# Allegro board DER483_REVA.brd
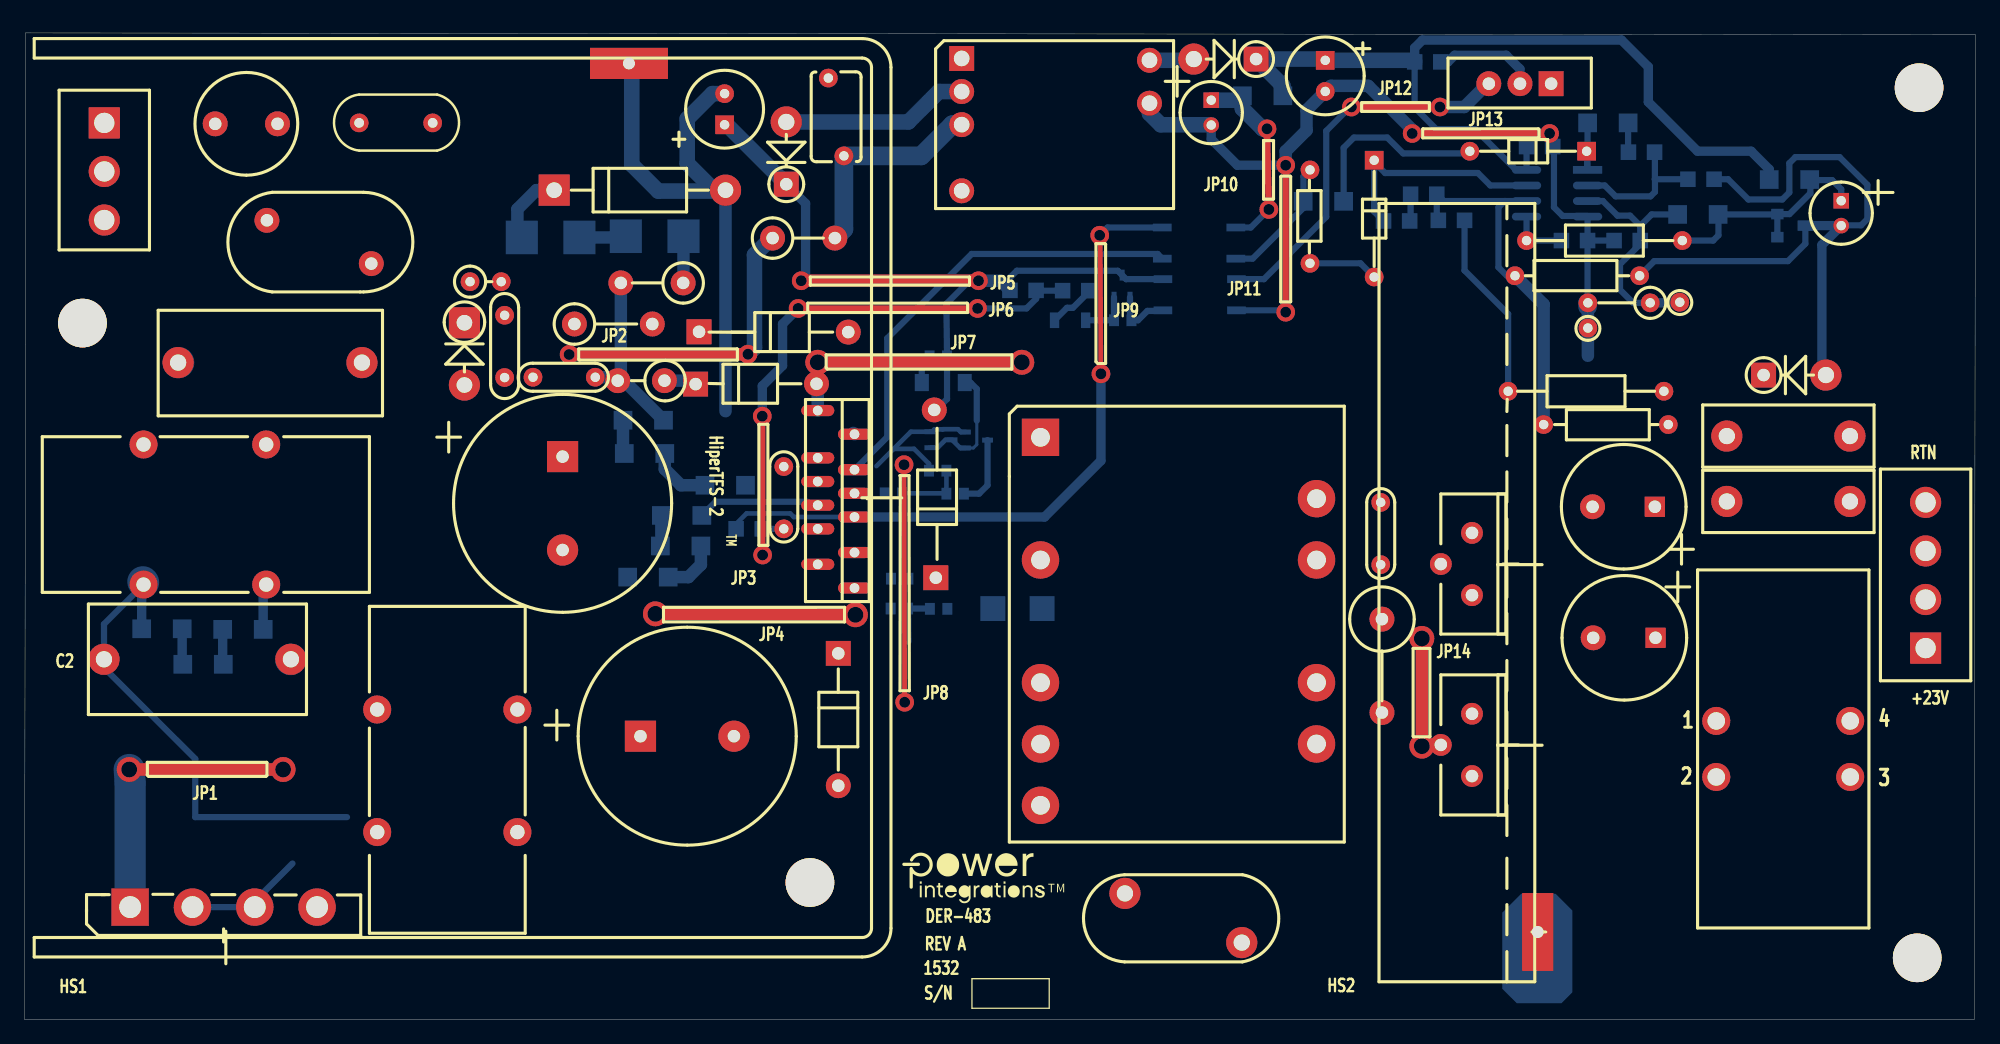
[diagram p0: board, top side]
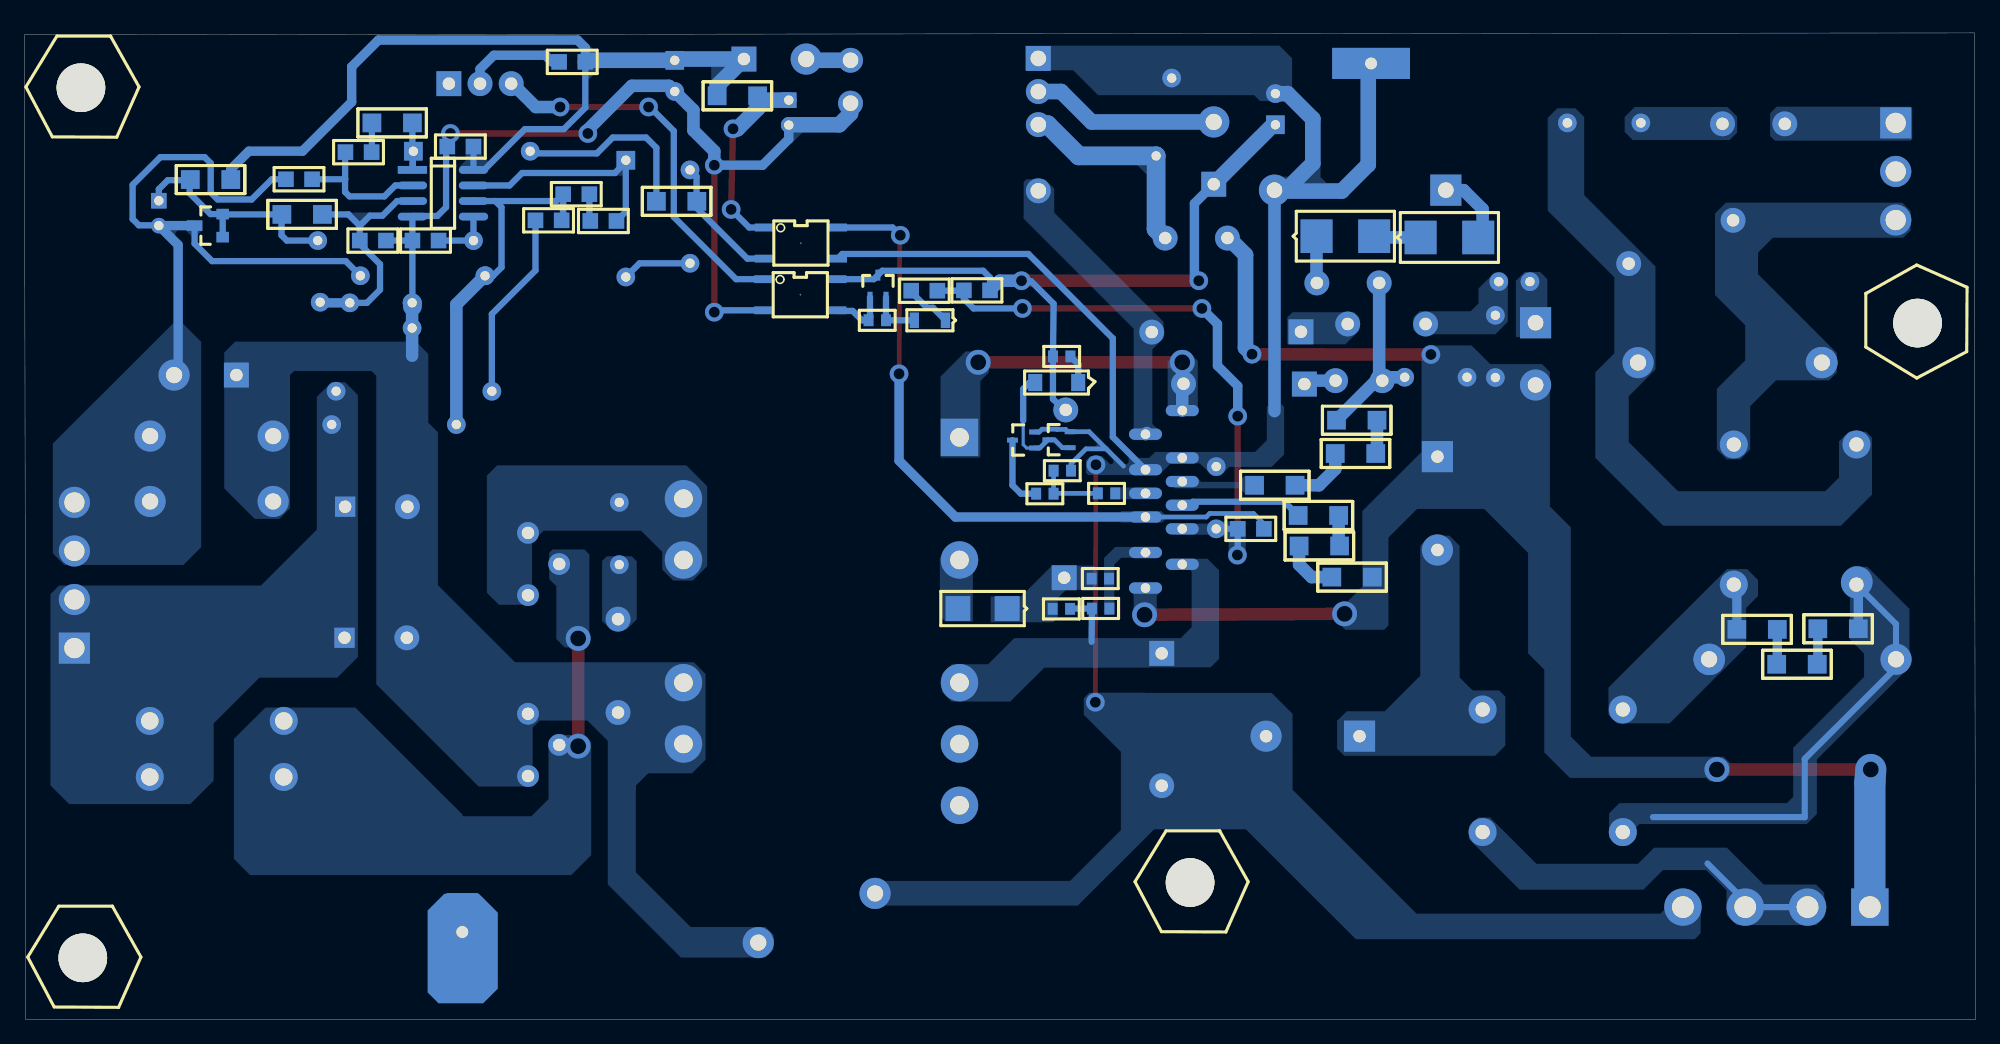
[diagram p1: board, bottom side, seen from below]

Outline 159.05 x 80.49 mm; copper layers: TOP, BOTTOM. Coordinates in mm from the lower left corner of the outline.
Outline path: 0,0 0.08,55.09 0.08,80.49 159.05,80.34 158.95,0 0,0

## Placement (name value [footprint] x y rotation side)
BR1  GBU8J  [PIDAXBRIDGEGBU8]  8.61 9.17 0 top
C1  220 nF  [PINPXCAPRAD720X340590040]  27.51 53.59 180 top
C2  470 nF  [PI_NP_CAP700X355LS600D040]  21.72 29.39 180 top
C3  560 uf  [PIPOLCAPCLYD710LS300040]  43.87 45.92 270 top
C4  560 uf  [PIPOLCAPCLYD710LS300040]  50.22 23.11 0 top
C5  2.2 nF  [PINPCAPRAD200X100200030]  46.53 52.4 180 top
C6  10 uF  [PINPCAPRAD200X100200030]  61.9 40.03 90 top
C7  100 nF  [PISMC0603]  70.61 33.53 0 bottom
C8  100 nF  [PISMC0603]  75.23 33.5 180 bottom
C9  2.2 nF  [PINPCAPRAD350X100200030]  39.14 52.37 90 top
C10  1.0 nF  [PINPCAPRAD290X160250030]  65.53 76.81 270 top
C11  10 nF  [PISMC0603]  75.16 44.78 180 bottom
C12  150 uF  [PIPOLCAPCYLD250LS100030]  57.07 73 90 top
C13  4.7 nF  [PINPCAPRAD640X260375040]  89.71 10.31 0 top
C14  1 nF  [PINPCAPRAD250X100200030]  110.57 42.19 270 top
C15  330 uF  [PIPOLCAPCYLD400LS200040]  132.97 31.14 180 top
C16  330 uF  [PIPOLCAPCYLD400LS200040]  132.92 41.83 180 top
C17  10 uF  [PIPOLCAPCLYD200LS80030]  96.75 75.01 270 top
C18  10 nf  [PISMC0805]  110.79 65.15 0 bottom
C19  2.2 nF  [PISMC0805]  115.27 65.2 0 bottom
C20  10 nf  [PISMC0805]  127.43 63.55 180 bottom
C21  150 uF  [PIPOLCAPCYLD250LS100030]  106.05 78.26 270 top
C22  10 nf  [PISMC0805]  130.76 70.76 0 bottom
C23  100 nF  [PISMC0805]  122.45 71.22 0 bottom
C24  100 nF  [PISMC0805]  129.59 63.55 0 bottom
C25  10 uF  [PIPOLCAPCLYD200LS80030]  148.11 66.8 270 top
D1  BAV19WS  [PISMSOD323]  83.97 57.05 0 bottom
D2  1N4007  [PIDAX475X125040DO41#2]  53.77 51.87 0 top
D3  US1D  [PISMDSMA]  78.94 33.53 0 bottom
D4  UF4005  [PIDAX475X125040DO41#3]  66.34 29.87 270 top
D5  UF4005  [PIDAX475X125040DO41]  74.3 36.04 90 top
D6  1N4007  [PIDV200X110X040DO41#2]  56.36 56.08 0 top
D7  UF4003  [PIDV200X110X040DO41]  62.1 68.15 90 top
D8  STPS30150CT  [PIDVTO2203VF1]  118.01 37.16 270 top
D9  STPS30150CT  [PIDVTO2203VF1]  118.01 22.4 270 top
D10  1N4148  [PIDAX375X070030DO35]  127.36 70.84 180 top
D11  1N4148  [PIDAX375X070030DO35]  110.03 70.1 270 top
D12  UF4003  [PIDV200X110X040DO41]  100.41 78.36 180 top
D13  1N4002-E3/54  [PIDV200X110X040DO41]  141.78 52.58 0 top
F1  5 A  [PI_TR5_SUBMIN_FUSE]  15.54 73.08 0 top
HS1  HEATSINK, W/PEM NUT AND EYELET, PI CUST  [PI_HS_DER483_BRIDGE_ESIP]  0.79 80.04 270 top
HS2  HEATSINK, W/PEM NUT AND EYELET, PI CUST  [PI_HS_DER483_DIODES]  123.14 3.07 90 top
J1  CON3  [PI_HDR_3PIN]  6.5 73.15 180 top
J2  CON4  [PI_HDR_4PIN]  154.99 30.3 0 top
J3  Rp  [PI_HOLE_30AWG]  127.46 56.41 0 top
J4  PCB Terminal 30 AWG  [PI_HOLE_30AWG]  134.95 58.52 0 top
L1  9 mH  [PI_IND_4P_500X1050LS450D46]  9.7 35.48 90 top
L2  9 mH  [PI_IND_4P_500X1050LS450D46]  40.18 15.29 180 top
L3  41 uH  [PI_IND_4P_TOROIDAL]  143.38 22.07 0 top
NOREF  -  []  -0.03 0.03 0 top
NOREF#2  -  []  -150.38 42.55 0 top
NOREF#3  -  []  -0.03 0.03 90 top
NOREF#4  -  []  71.58 14.05 0 top
NOREF#5  -  []  -228.19 -156.46 0 top
POST1  Post Hex, 6-32, snap, 0.375L, NYL  [PIMTGHOLED156]  64.03 11.18 180 bottom
POST2  Post Hex, 6-32, snap, 0.375L, NYL  [PIMTGHOLED156]  154.46 76.02 180 bottom
POST3  Post Hex, 6-32, snap, 0.375L, NYL  [PIMTGHOLED156]  154.31 5.03 180 bottom
POST4  Post Hex, 6-32, snap, 0.375L, NYL  [PIMTGHOLED156]  4.72 56.82 90 bottom
Q1  MMST3904  [PISMSOT323132]  76.71 46.61 90 bottom
Q2  MMST3904  [PISMSOT323132]  73.81 46.63 90 bottom
Q3  MMST3904  [PISMSOT323132]  90.14 58.93 180 bottom
R1  680 k  [PISMR1206]  9.55 31.88 0 bottom
R2  680 k  [PISMR1206]  12.9 28.98 0 bottom
R3  680 k  [PISMR1206]  16.15 31.83 0 bottom
R4  931 k  [PISMR1206]  52.48 36.09 180 bottom
R5  931 k  [PISMR1206]  55.14 38.63 180 bottom
R6  976 k  [PISMR1206]  51.92 41.12 0 bottom
R7  100  [PI12WRESD180LS675D040]  53.7 60.1 180 top
R8  2.2  [PI12WVRESD180LS150D040]  48.36 52.12 0 top
R9  931 k  [PISMR1206]  52.1 48.89 180 bottom
R10  931 k  [PISMR1206]  48.9 46.18 0 bottom
R11  976 k  [PISMR1206]  58.78 43.59 180 bottom
R12  7.5 k  [PISMR0805]  80.34 59.49 0 bottom
R13  47 k  [PISMR0603]  90.25 57.05 180 bottom
R14  1.2 k  [PISMR0805]  84.63 59.46 0 bottom
R15  232 k  [PISMR0805]  60.15 40.03 180 bottom
R16  1 k  [PISMR0603]  70.64 35.97 0 bottom
R17  22 k  [PI14WVRESD100LS100D030]  36.32 60.2 0 top
R18  6.8  [PI12WVRESD180LS150D040#2]  44.83 56.74 0 top
R19  2.2  [PI12WVRESD180LS150D040#3]  60.99 63.75 0 top
R20  4.7 k  [PISMR0603]  71.55 42.93 180 bottom
R21  4.7 k  [PISMR0603]  76.58 42.9 180 bottom
R22  1 k  [PISMR0603]  75.21 54.1 180 bottom
R23  4.7  [PI1WVRESD200LS200D040]  110.67 32.66 270 top
R24  220  [PISMR1206]  99.29 75.36 0 bottom
R25  4.7 k  [PISMR1206]  107.54 66.75 180 bottom
R26  3.3 k  [PI18WRESD080LS300D030]  104.8 69.32 270 top
R27  82.5 k  [PI14WRESD100LS500D030]  134.01 48.54 180 top
R28  10 k  [PI14WVRESD100LS100D030#2]  120.95 51.26 0 top
R29  3.3 k  [PISMR0805]  113 67.34 0 bottom
R30  10.0 k  [PI14WRESD100LS400D030]  121.51 60.68 0 top
R31  4.7 k  [PI14WRESD100LS500D030#2]  135.15 63.55 180 top
R32  4.7 k  [PISMR1206]  142.24 68.53 0 bottom
R33  105 k  [PISMR1206]  134.77 65.68 0 bottom
R34  6.8 k  [PISMR1206]  127.43 73.15 0 bottom
R35  10 k  [PISMR0805]  135.61 68.55 0 bottom
R36  5.11 k  [PI14WRESD100LS400D030#2]  132.54 58.47 180 top
R37  0.03  [PI_5W_RES_550X200LS394D040]  138.79 42.27 0 top
R38  0.03  [PI_5W_RES_550X200LS394D040]  138.79 47.6 0 top
R39  10 k  [PISMR0805]  113.33 78.13 0 bottom
RT1  2.5  [PI_RAD180X395LS235D031]  27.28 73.15 0 top
RV1  175 VAC  [PI_DISC_575X320_LS335X140D040]  28.27 61.67 180 top
SW1  SPDT SLIDE  [PI_SWITCH_SPDT_SLIDE_PCBM_1]  124.46 76.35 90 top
T1  EER28L  [PI_BOBBIN_EER28L_14P_DER483]  82.83 47.5 0 top
T2  EF12.6  [PI_BOBBIN_EF126_9P_DER483]  76.4 78.41 0 top
U1  TFS-7704H  [PI_IC_ESIP16-12_OVAL_SLOT]  67.67 49.68 270 top
U2  PC357A  [PI_4_SMD]  95.76 63.35 270 bottom
U3  PC357A  [PI_4_SMD]  95.81 59.13 270 bottom
U4  LM431AIM3DR  [PISMSOT23123]  142.9 65.71 90 bottom
U5  LM358D  [PISMSO8]  127.43 69.32 270 bottom
VR1  SMBJ150A  [PISMDO214AA12]  53.72 63.91 180 bottom
VR2  MMSZ5245B-7-F  [PI_SM_SOD-123_12]  73.15 51.97 0 bottom
VR3  P6KE150A  [PIDV200X140X050DO15DO204AC]  35.86 56.85 270 top
VR5  SMBJ150A  [PISMDO214AA12]  45.24 63.8 180 bottom
VR6  P6KE170A  [PIDAX550X140050DO15DO204AC]  43.18 67.67 0 top

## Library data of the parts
BR1 = DISCRETE BRIDGE_+~~-
C1 C5-C11 C13 C14 C18-C20 C22-C24 = CAP NP
C2 = CAP NP: tolerance: 20
C3 C4 = CAP POL
C12 C21 = CAP POL: tolerance: 20
C15 C16 = CAP POL: alternate symbols: (pipolcapclyd395x630ls200030h)
C17 C25 = CAP POL: alternate symbols: (pipolcapclyd200ls80030h)
D1 D3 = DIODE
D2 D6 D7 D12 D13 = DIODE: alternate symbols: (pidax475x125040do41,pidv200x110x040do41wbead,pidax390x125040do41)
D4 D5 = DIODE: alternate symbols: (pidax475x125040do41,pidax390x125040do41)
D8 D9 = DS_DUAL_CK_A_AC: alternate symbols: (pidvto2203vf1)
D10 D11 = DIODE: alternate symbols: (pidax375x070030do35,pidv100x080x030do35)
F1 = FUSE
HS1 HS2 = HS-PI_CUSTOM1
J1 = CON3
J2 = CON4
J3 J4 = TERM_1Pin
L1 L2 = INDUCTOR_4P_REVB_0
L3 = INDUCTOR_4P_SD
POST1-POST4 = POST_CRKT_BRD_6-32_HEX
Q1-Q3 = NPN_BEC
R1-R4 R9-R15 R20-R22 R24 R25 R29 R32-R34 R37-R39 = R
R5 R6 R35 = R: tolerance: 1%
R7 R8 R18 R19 = R: alternate symbols: (pi12wvresd180ls200d040,pi12wvresd180ls250d040,pi12wresd180ls675d040)
R16 = R: tolerance: 5%
R17 R27 R28 R30 R31 R36 = R: alternate symbols: (pi14wvresd100ls200d030,pi14wresd100ls400d030,pi14wresd100ls500d030)
R23 = R: alternate symbols: (pi1wvresd120ls200d040,pi1wvresd120ls300d040,pi1wvresd200ls200d040,pi1wvresd200ls300d040,pi1wvresd200ls350d040)
R26 = R: alternate symbols: (pi18wresd080ls300d030)
RT1 = THERMISTOR
RV1 = VARISTOR
SW1 = SW SLIDE-SPDT
T1 = BEER28L_CUSTOM_DER483
T2 = BEF12.6_CUSTOM_DER483
U1 = HiperTFS_II_I_2_ROW_2: alternate symbols: (pi_ic_esip16-12_oval_slot_recpt)
U2 U3 = OPTO_A_B
U4 = TL431/SOT-23_CAR: tolerance: 2%
U5 = LM358
VR1 VR2 VR5 = DIODE_ZENER
VR3 VR6 = DIODE_ZENER: alternate symbols: (pidax550x140050do15do204ac)

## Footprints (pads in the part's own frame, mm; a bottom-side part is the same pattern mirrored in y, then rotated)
PI1WVRESD200LS200D040
  round 2.032 hole 1.016: 1(0,0) 2(7.62,0)
PI12WRESD180LS675D040
  round 2.032 hole 1.016: 1(0,0) 2(5.08,0)
PI12WVRESD180LS150D040
  round 2.032 hole 1.016: 1(0,0) 2(3.81,0)
PI12WVRESD180LS150D040#2
  round 2.032 hole 1.016: 1(0,0) 2(6.35,0)
PI12WVRESD180LS150D040#3
  round 2.032 hole 1.016: 1(0,0) 2(5.08,0)
PI14WRESD100LS400D030
  round 1.524 hole 0.762: 1(0,0) 2(10.16,0)
PI14WRESD100LS400D030#2
  round 1.524 hole 0.762: 1(0,0) 2(5.08,0)
PI14WRESD100LS500D030
  round 1.524 hole 0.762: 1(0,0) 2(10.16,0)
PI14WRESD100LS500D030#2
  round 1.524 hole 0.762: 1(0,0) 2(12.7,0)
PI14WVRESD100LS100D030
  round 1.524 hole 0.762: 1(0,0) 2(2.54,0)
PI14WVRESD100LS100D030#2
  round 1.524 hole 0.762: 1(0,0) 2(12.7,0)
PI18WRESD080LS300D030
  round 1.524 hole 0.762: 1(0,0) 2(7.62,0)
PI_4_SMD
  rect 0.635x1.524 smd: 1(-1.27,-2.997) 2(1.27,-2.997) 3(1.27,2.997) 4(-1.27,2.997)
PI_5W_RES_550X200LS394D040
  round 2.54 hole 1.321: 1(0,0) 2(10.033,0)
PI_BOBBIN_EER28L_14P_DER483
  round 3.048 hole 1.524: (0,-25.019) (0,-30.023) 3(0,-10.008) 5(0,-20.015) 9(22.504,-25.019) 10(22.504,-20.015) 12(22.504,-10.008) 13(22.504,-5.004)
  rect 3.048x3.048 hole 1.524: 1(0,0)
PI_BOBBIN_EF126_9P_DER483
  rect 2.032x2.032 hole 1.27: 1(0,0)
  round 2.032 hole 1.27: 2(0,-2.7) 3(0,-5.4) 5(0,-10.8) 8(15.311,-3.65) 9(15.311,-0.15)
PI_DISC_575X320_LS335X140D040
  round 2.032 hole 1.016: 1(0,0) 2(8.509,-3.531)
PI_HDR_3PIN
  rect 2.54x2.54 hole 1.651: 1(0,0)
  round 2.54 hole 1.651: 2(0,3.962) 3(0,7.925)
PI_HDR_4PIN
  rect 2.54x2.54 hole 1.651: 1(0,0)
  round 2.54 hole 1.651: 2(0,3.962) 3(0,7.925) 4(0,11.887)
PI_HOLE_30AWG
  round 1.524 hole 0.762: 1(0,0)
PI_HS_DER483_BRIDGE_ESIP
  rect 2.54x6.35 hole 0.965: 1(2.032,48.489)
PI_HS_DER483_DIODES
  rect 6.35x2.54 hole 0.965: 1(4.064,-0.229)
PI_IC_ESIP16-12_OVAL_SLOT
  oval 0.914x2.692 hole 0.787: 1(0,-2.997) 3(1.93,0) 5(3.861,-2.997) 6(4.826,0) 7(5.791,-2.997) 8(6.756,0) 9(7.722,-2.997) 10(8.687,0) 11(9.652,-2.997) 13(11.582,0) 14(12.548,-2.997) 16(14.478,0)
PI_IND_4P_500X1050LS450D46
  round 2.286 hole 1.168: 1(0,0) 2(11.43,-10) 3(11.43,0) 4(0,-10)
PI_IND_4P_TOROIDAL
  round 2.286 hole 1.422: 1(-5.461,2.286) 2(-5.461,-2.286) 3(5.461,-2.286) 4(5.461,2.286)
PI_NP_CAP700X355LS600D040
  round 2.54 hole 1.321: 1(0,0) 2(15.24,0)
PI_RAD180X395LS235D031
  round 1.524 hole 0.787: 1(0,0) 2(5.994,0)
PI_SM_SOD-123_12
  rect 1.143x1.397 smd: 1(0,0) 2(3.505,0)
PI_SWITCH_SPDT_SLIDE_PCBM_1
  rect 2.032x2.032 hole 1.016: 1(0,0)
  round 2.032 hole 1.016: 2(0,2.54) 3(0,5.08)
PI_TR5_SUBMIN_FUSE
  round 2.032 hole 1.016: 1(0,0) 2(5.08,0)
PIDAX375X070030DO35
  rect 1.524x1.524 hole 0.762: 1(0,0)
  round 1.524 hole 0.762: 2(9.525,0)
PIDAX475X125040DO41
  rect 2.032x2.032 hole 1.016: 1(0,0)
  round 2.032 hole 1.016: 2(13.691,0.127)
PIDAX475X125040DO41#2
  rect 2.032x2.032 hole 1.016: 1(0.94,-0.025)
  round 2.032 hole 1.016: 2(10.795,0)
PIDAX475X125040DO41#3
  rect 2.032x2.032 hole 1.016: 1(0,0)
  round 2.032 hole 1.016: 2(10.795,0)
PIDAX550X140050DO15DO204AC
  rect 2.54x2.54 hole 1.27: 1(0,0)
  round 2.54 hole 1.27: 2(13.97,0)
PIDAXBRIDGEGBU8
  rect 3.048x3.048 hole 1.778: 1(0,0)
  round 3.048 hole 1.778: 2(5.08,0) 3(10.16,0) 4(15.24,0)
PIDV200X110X040DO41
  rect 2.032x2.032 hole 1.016: 1(0,0)
  round 2.54 hole 1.321: 2(5.08,0)
PIDV200X110X040DO41#2
  rect 2.032x2.032 hole 1.016: 1(-1.372,0.025)
  round 2.032 hole 1.016: 2(10.795,0)
PIDV200X140X050DO15DO204AC
  rect 2.54x2.54 hole 1.27: 1(0,0)
  round 2.54 hole 1.27: 2(5.08,0)
PIDVTO2203VF1
  round 1.778 hole 1.016: 1(-2.54,0) 2(0,-2.54) 3(2.54,0)
PIMTGHOLED156
  round 3.962 hole 3.962: 1(0,0)
PINPCAPRAD200X100200030
  round 1.524 hole 0.762: 1(0,0) 2(5.08,0)
PINPCAPRAD250X100200030
  round 1.524 hole 0.762: 1(0,0) 2(5.08,0)
PINPCAPRAD290X160250030
  round 1.524 hole 0.762: 1(0,0) 2(6.35,1.27)
PINPCAPRAD350X100200030
  round 1.524 hole 0.762: 1(0,0) 2(5.08,0)
PINPCAPRAD640X260375040
  round 2.54 hole 1.321: 1(0,-0.025) 2(9.525,-4.039)
PINPXCAPRAD720X340590040
  round 2.54 hole 1.321: 1(0,0) 2(14.986,0)
PIPOLCAPCLYD200LS80030
  rect 1.27x1.27 hole 0.762: 1(0,0)
  round 1.27 hole 0.762: 2(2.032,0)
PIPOLCAPCLYD710LS300040
  rect 2.54x2.54 hole 1.016: 1(0,0)
  round 2.54 hole 1.016: 2(7.62,0)
PIPOLCAPCYLD250LS100030
  rect 1.524x1.524 hole 0.762: 1(0,0)
  round 1.524 hole 0.762: 2(2.54,0)
PIPOLCAPCYLD400LS200040
  rect 1.651x1.651 hole 1.016: 1(0,0)
  round 2.032 hole 1.016: 2(5.08,0)
PISMC0603
  rect 0.813x0.965 smd: 1(0,0) 2(1.422,0)
PISMC0805
  rect 1.27x1.27 smd: 1(0,0) 2(2.134,0)
PISMDO214AA12
  rect 2.616x2.743 smd: 1(0,0) 2(4.699,0)
PISMDSMA
  rect 2.032x2.032 smd: 1(0,0) 2(4.013,0)
PISMR0603
  rect 0.813x0.965 smd: 1(0,0) 2(1.422,0)
PISMR0805
  rect 1.27x1.27 smd: 1(0,0) 2(2.134,0)
PISMR1206
  rect 1.524x1.524 smd: 1(0,0) 2(3.302,0)
PISMSO8
  rect 0.635x2.388 smd: 1(0,0)
  oval 0.635x2.388 smd: 2(1.27,0) 3(2.54,0) 4(3.81,0) 5(3.81,4.978) 6(2.54,4.978) 7(1.27,4.978) 8(0,4.978)
PISMSOD323
  rect 0.762x1.27 smd: 1(0,0) 2(2.54,0)
PISMSOT23123
  rect 0.864x1.016 smd: 1(-1.88,0) 3(0,0)
  rect 0.864x1.27 smd: 2(-0.94,2.286)
PISMSOT323132
  rect 0.406x0.889 smd: 1(0.018,0) 2(1.321,0) 3(0.66,1.803)

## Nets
VCC: C21.1 C23.1 D12.1 R24.2 R32.1 R39.1 U5.8(V+)
VCCPR: C12.1 D5.2 D7.1 Q3.3(COLLECTOR) R12.1 R22.1 U3.4(C)
N5956925: BR1.4(-DC) C4.2 C6.2 C10.1 C11.2 C12.2 C13.1 D4.2 HS1.1 Q1.2(EMITTER) Q2.2(EMITTER) T2.1 U1.5(G) U1.6(S) U2.3(E) VR6.2
N6240208: R5.2 R6.1
N6451090: C13.2 C15.2 C16.2 C17.2 C20.1 C21.2 C23.2 C24.1 D9.1(A1) D9.3(A2) D13.1 J3.1 R23.2 R36.2 R37.1 R38.1 T1.9 T1.10 T2.8 U3.2(C) U5.4(V-)
N6900286: BR1.1(+DC) C3.1 C5.2 C9.1 R4.2 R19.1 U1.16(HD) VR3.2
N7093005: C25.2 D13.2 J2.3 J2.4 R30.2 R35.2 R37.2 R38.2 U4.2(A)
N8059193: C1.1 L1.3 RT1.2 RV1.1
N8059197: F1.1 J1.1
N8059233: C2.1 L1.4 L2.2 R3.2
N8059379: R1.2 R2.1
N8059399: R2.2 R3.1
N8059437: C1.2 J1.3 L1.2 RV1.2
N8059489: C2.2 L1.1 L2.3 R1.1
N8060888: BR1.2(AC1) BR1.3(AC2) L2.1
N8067300: C15.1 C16.1 J2.1 J2.2 L3.3 L3.4 R27.1 R28.2
N8070264: D10.2 R25.1
N8070276: C25.1 R31.1 R32.2 R33.2 U4.1(C) U4.3(VREF)
N8070304: C18.1 D11.1 U5.7(OUT)
N8070334: C19.1 R27.2 R29.2 R30.1 U5.6(-IN)
N8070466: C20.2 R31.2 U5.5(+IN)
N8070478: R25.2 R26.1 U2.2(C)
N8070490: D10.1 R34.1 U5.1(OUT)
N8070648: C22.2 R35.1 U5.2(-IN)
N8071028: C24.2 J4.1 R33.1 R36.1 U5.3(+IN)
N8073566: C3.2 C4.1 L2.4
N8079055: C17.1 R24.1 U2.1(A)
N8088388: F1.2 RT1.1
N8130547: R39.2 SW1.2
N8135210: C22.1 R34.2
N8194184: C7.2 C8.2 D4.1 T1.5 U1.14(HS)
N8194788: D2.2 T1.1 U1.1(D)
N8195110: D6.2 T2.5 U1.3(DSB)
N8203179: C14.1 D8.1(A1) D8.3(A2) T1.12 T1.13
N8204013: D7.2 T2.2
N8204160: Q1.1(BASE) Q2.1(BASE) Q2.3(COLLECTOR) VR2.2
N8204208: R20.2 U1.8(EN)
N8204226: Q1.3(COLLECTOR) R21.1
N8207135: C8.1 D3.1 D5.1 R16.2
N8207503: C7.1 R16.1 U1.13(VDDH)
N8207747: C6.1 R12.2 R14.1 R15.1 U1.11(BP)
N8207786: R15.2 U1.10(FB) U2.4(C)
N8210623: C9.2 R17.2 R18.1
N8210650: C10.2 R19.2 T2.3
N8210678: D6.1 R18.2
N8213244: C11.1 R20.1 R21.2
N8214579: R10.2 R11.2
N8215069: R11.1 U1.7(R)
N8245190: R4.1 R5.1
N8273380: R6.2 U1.9(L)
N8278408: SW1.3 U3.1(A)
N8282330: VR1.2 VR5.1
N8282334: C5.1 R7.2 R8.1 R9.1
N8284139: Q3.1(BASE) R13.1 U3.3(E)
N8284357: R7.1 VR1.1
N8284401: VR5.2 VR6.1
N8289100: D8.2(K) D9.2(K) L3.1 L3.2
N8290901: C14.2 R23.1
N8295742: R9.2 R10.1
N8298855: D1.2 Q3.2(EMITTER) R13.2
N8307586: D2.1 R8.2
N8312003: D1.1 R14.2
N8332239: D11.2 R26.2
N8339978: C18.2 R29.1
N8340626: C19.2 R28.1
N8356117: D12.2 T2.9
N8358108: D3.2 T1.3
N80948331: R22.2 VR2.1
N82099951: R17.1 VR3.1

Pads without a net: HS2 1; J1 2; POST1 1; POST2 1; POST3 1; POST4 1; SW1 1

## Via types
v1: diameter 2.032, hole 1.295, TOP to BOTTOM, 8 vias
v2: diameter 1.524, hole 0.889, TOP to BOTTOM, 20 vias

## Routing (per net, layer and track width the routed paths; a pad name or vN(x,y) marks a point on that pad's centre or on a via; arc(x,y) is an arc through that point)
VCC: length 71
  BOTTOM w0.508: R39.1 113.33,74.4 115.09,72.64 118.26,72.64 121.59,69.32 U5.8 C23.1
  BOTTOM w0.762: R39.1 113.33,79.27 113.97,79.91 130.2,79.91 132.38,77.72 132.38,74.85 136.4,70.84 140.77,70.84 142.24,69.37 R32.1
  BOTTOM w1.27: R39.1 113.21,78.26 C21.1 105.94,78.36 D12.1 102.59,76.17 R24.2
VCCPR: length 61.5
  TOP w1.016: v2(63.32,60.27) v2(77.77,60.27)
  BOTTOM w0.508: R12.1 80.34,60.53 80.9,61.09 89.13,61.09 Q3.3 89.81,60.4 U3.4 ; D5.2 74.24,49.66 75.21,50.62 R22.1 75.16,58.39 76.99,60.22 79.6,60.22
  BOTTOM w0.762: v2(63.32,60.27) 63.68,60.63 63.68,66.57 D7.1
  BOTTOM w1.016: R12.1 79.55,60.27 v2(77.77,60.27)
  BOTTOM w1.27: D7.1 57.25,73 C12.1
N5956925: length 115.8
  TOP w0.381: v2(71.7,45.26) v2(71.75,25.88)
  BOTTOM w0.381: 70.87,46.56 69.46,45.15 ; 70.87,46.56 72.26,47.96 Q2.2 73.99,47.96 74.18,48.15 74.87,48.15 74.88,48.16 76.1,48.16 76.33,47.93 Q1.2 ; 70.87,46.56 72.52,46.56 73.74,45.34 C11.2
  BOTTOM w0.508: 67.67,44.86 70.33,47.52 70.33,55.58 77.22,62.46 92.38,62.46 U2.3
  BOTTOM w1.016: 57.15,49.63 VR6.2 ; 57.07,75.44 57.15,75.36
  BOTTOM w1.27: HS1.1 49.5,77.77 49.5,69.75 51.66,67.59 57.07,67.59 VR6.2 56.21,67.67 54.03,69.85 54.03,73.48 56.08,75.54 C12.2
N6240208: length 2.5
  BOTTOM w1.016: R5.2 51.92,38.71 R6.1
N6451090: length 81.2
  TOP w0.508: v2(102.82,57.71) v2(102.82,69.7) ; v2(113.13,72.29) v2(124.33,72.29)
  BOTTOM w0.508: v2(124.33,72.29) 124.33,71.48 C23.2 124.69,71.12 124.69,66.27 125.4,65.56 127.38,65.56 U5.4 C20.1 ; 127.41,58.14 127.43,58.17 ; U3.2 102.67,57.86 v2(102.82,57.71) ; C20.1 C24.1 ; C20.1 127.43,58.45
  BOTTOM w0.762: v2(102.82,69.7) 98.88,69.7 96.75,71.83 C17.2
  BOTTOM w1.016: v2(113.13,72.29) 113.13,72.59 109.55,76.17 106.5,76.17 C21.2 104.52,74.19 104.52,72.54 102.82,70.84 v2(102.82,69.7) ; R36.2 J3.1 127.46,54.15
  BOTTOM w1.27: T2.8 91.71,73.92 92.63,73 96.72,73 C17.2
  BOTTOM w1.524: 127.43,58.17 127.43,58.45 R36.2
N6900286: length 65
  TOP w1.016: v1(8.53,20.4) v1(21.08,20.4) ; v1(67.74,33.02) v1(51.44,33.1) ; v2(58.98,54.28) v2(44.4,54.25)
  BOTTOM w1.27: v2(58.98,54.28) 59.51,54.81 59.51,62.38 60.88,63.75 R19.1
  BOTTOM w2.54: BR1.1 8.61,19.3 v1(8.53,20.4)
N7093005: length 54.1
  BOTTOM w0.508: R35.2 138.89,68.55 140.54,66.9 143.31,66.9 143.88,67.48 143.88,69.86 144.37,70.36 147.98,70.36 150.24,68.1 150.24,65.3 149.73,64.8 148.13,64.8 C25.2 ; U4.2 145.19,63.3 143.76,61.87 132.87,61.87 R30.2
  BOTTOM w0.762: D13.2 146.91,52.63 146.53,53.01 146.53,63.2 C25.2 U4.2
N8059233: length 3.8
  BOTTOM w0.762: R3.2 19.46,35.24 L1.4
  BOTTOM w2.54: 21.69,29.36 C2.1
N8059379: length 2.9
  BOTTOM w0.762: R1.2 12.85,29.03 R2.1
N8059399: length 2.9
  BOTTOM w0.762: R2.2 16.15,29.03 R3.1
N8059437: length 0.1
  BOTTOM w2.54: C1.2 12.57,53.59
N8059489: length 39.7
  BOTTOM w0.508: 9.55,35.33 6.48,32.26 C2.2 6.48,28.7 13.92,21.26 13.92,16.51 26.29,16.51
  BOTTOM w0.762: C2.2 6.73,29.39 ; 9.7,35.66 L1.1 9.55,35.33 R1.1
  BOTTOM w2.54: 9.65,35.71 9.7,35.66
N8060888: length 9.9
  BOTTOM w0.508: 21.84,12.73 18.77,9.65 BR1.3 BR1.2
N8070264: length 15.6
  BOTTOM w0.508: R25.1 107.54,71.12 108.38,71.96 111.1,71.96 112.39,70.66 117.65,70.66 D10.2
N8070276: length 19.8
  BOTTOM w0.508: U4.3 U4.1 ; U4.3 142.88,65.68 R33.2 138.1,65.66 138.1,63.98 137.67,63.55 R31.1 ; U4.3 143.89,65.71 145.59,67.41 145.59,68.48 ; 145.59,68.48 147.37,68.48 148.11,67.74 C25.1 ; 145.59,68.48 R32.2
N8070304: length 18.5
  BOTTOM w0.508: D11.1 110.03,69.95 ; 110.03,69.95 110.03,65.91 C18.1 ; 110.03,69.95 110.92,69.06 118.49,69.06 119.51,68.05 U5.7
N8070334: length 30.1
  BOTTOM w0.508: C19.1 115.14,65.33 R29.2 115.7,66.78 120.68,66.78 ; 122.43,66.8 U5.6 120.68,66.78 ; 120.68,66.78 120.17,66.27 120.17,61.37 120.85,60.68 121.49,60.68
  BOTTOM w1.016: R30.1 123.85,58.34 R27.2
  BOTTOM w1.524: 121.49,60.68 R30.1
N8070466: length 4.8
  BOTTOM w0.508: U5.5 R31.2 C20.2
N8070478: length 10.5
  BOTTOM w0.508: U2.2 100.13,62.08 104.24,66.19 R25.2 104.27,66.78 104.27,68.78 R26.1
N8070490: length 5.5
  BOTTOM w0.508: 127.41,70.92 127.41,69.34 U5.1 D10.1 127.43,70.92 R34.1
N8070648: length 12
  BOTTOM w0.508: 132.92,68.55 132.92,70.74 C22.2 ; 132.92,68.55 R35.1 ; 132.92,68.55 132.92,68.55 132.92,67.52 132.56,67.16 129.72,67.16 128.83,68.05 U5.2
N8071028: length 19.8
  BOTTOM w0.508: 131.72,64.75 130.9,65.58 129.87,65.58 128.68,66.78 U5.3 ; 131.72,64.75 132.65,65.68 R33.1 ; 131.72,64.75 C24.2 131.72,63.27 130.07,61.62 130.07,59.54 131.14,58.47 R36.1
  BOTTOM w0.762: R36.1 134.9,58.47 J4.1
N8079055: length 16.3
  TOP w0.508: v2(101.45,66.09) v2(101.3,72.67)
  BOTTOM w0.508: v2(101.45,66.09) 99.97,64.62 U2.1
  BOTTOM w1.27: v2(101.3,72.67) 100.94,72.67 99.29,74.32 R24.1 98.93,75.01 C17.1
N8130547: length 8.3
  BOTTOM w0.762: R39.2 116.05,78.13 116.59,78.67 120.79,78.67 121.92,77.55 SW1.2
N8135210: length 2.4
  BOTTOM w0.508: C22.1 130.73,70.79 R34.2
N8194184: length 4.8
  BOTTOM w0.508: 72.06,30.81 C7.2 73.79,33.53 C8.2
  BOTTOM w1.524: 66.14,30.07 D4.1
N8194788: length 20.6
  TOP w1.016: v1(64.67,53.62) v1(81.31,53.62)
  BOTTOM w1.016: v1(64.67,53.62) U1.1
N8195110: length 0.1
  BOTTOM w1.016: U1.3 67.56,47.85
N8204013: length 15.3
  BOTTOM w1.27: D7.2 72.06,73.23 74.54,75.71 T2.2
N8204160: length 10.2
  BOTTOM w0.254: Q1.1 77.36,46.63 77.64,46.9 77.64,48.87
  BOTTOM w0.381: Q1.1 76.28,46.63 Q2.3 75.08,47.29 74.44,46.65 Q2.1
  BOTTOM w0.508: VR2.2 77.11,51.97 77.64,51.45 77.64,48.87
N8204226: length 5.9
  BOTTOM w0.508: Q1.3 78.51,43.59 77.83,42.9 R21.1
N8207747: length 47.8
  TOP w0.508: v2(60.15,49.23) 60.15,37.92 v2(60.17,37.9) ; v2(77.7,58.01) v2(63.07,58.01)
  BOTTOM w0.508: v2(77.7,58.01) 81.69,58.01 82.47,58.8 R12.2 82.5,59.46 R14.1 ; v2(60.17,37.9) 60.15,37.92 R15.1 C6.1
  BOTTOM w0.762: v2(60.15,49.23) 60.15,51.69 61.8,53.34 61.8,56.74 v2(63.07,58.01)
N8207786: length 56.3
  TOP w0.381: v2(87.66,63.98) 87.7,63.84 v2(87.76,52.68)
  BOTTOM w0.381: U1.10 62.72,41 62.42,41.29 58.86,41.29 58.01,40.44 R15.2
  BOTTOM w0.508: v2(87.66,63.98) 88.29,64.62 U2.4
  BOTTOM w0.762: v2(87.76,52.68) 87.76,45.59 83.16,41 U1.10
N8210650: length 17.7
  BOTTOM w1.524: T2.3 75.65,73.01 73.1,70.46 C10.2 66.8,64.49 R19.2
N8213244: length 5.5
  BOTTOM w0.381: R20.1 75.13,42.93 R21.2 C11.1
N8214579: length 5.1
  BOTTOM w1.016: R11.2 53.52,43.59 52.2,44.91 R10.2
N8245190: length 4.6
  BOTTOM w1.016: R5.1 55.14,37.11 54.13,36.09 R4.1
N8273380: length 10
  BOTTOM w0.508: R6.2 56.34,42.24 63.8,42.24 64.08,41.96 U1.9
N8278408: length 31.4
  TOP w0.508: v2(115.39,74.45) v2(108.18,74.45)
  BOTTOM w0.508: v2(108.18,74.45) 107.65,74.02 106.12,72.49 106.12,65.48 101.04,60.4 U3.1
  BOTTOM w1.016: 119.35,76.43 119.28,76.35 ; 119.28,76.35 SW1.3 ; 119.28,76.35 117.37,74.45 v2(115.39,74.45)
N8282330: length 3.8
  BOTTOM w1.016: VR1.2 48.92,63.8 VR5.1
N8282334: length 15.1
  BOTTOM w1.016: R9.1 48.87,52.12 R8.1 ; R7.2 48.62,52.37 R8.1 ; R8.1 48.08,52.4 C5.1
N8284139: length 4.8
  BOTTOM w0.508: Q3.1 90.13,57.17 R13.1 90.78,57.05 91.54,57.81 92.76,57.81 U3.3
N8284357: length 3.8
  BOTTOM w1.016: R7.1 53.72,60.12 VR1.1
N8284401: length 6.1
  BOTTOM w1.016: VR6.1 41.73,67.67 40.18,66.12 40.18,64.16 VR5.2
N8289100: length 8.8
  TOP w1.016: v1(113.92,22.3) v1(113.92,31.09)
N8295742: length 2.8
  BOTTOM w1.016: R10.1 48.79,46.28 R9.2
N8298855: length 4.2
  BOTTOM w0.508: D1.2 R13.2 Q3.2
N8307586: length 2.7
  BOTTOM w0.508: D2.1 54.51,51.84
  BOTTOM w1.016: R8.2 54.23,52.12 54.56,51.79
N8312003: length 3.9
  BOTTOM w0.508: R14.2 86.77,59.36 85.47,58.06 84.99,58.06 D1.1
N8332239: length 5.7
  BOTTOM w0.508: D11.2 108.92,61.7 R26.2
N8339978: length 2.2
  BOTTOM w0.508: R29.1 113,65.23 C18.2
N8340626: length 15.4
  BOTTOM w0.508: C19.2 117.4,61.11 120.95,57.56 R28.1
N8356117: length 3.7
  BOTTOM w1.27: D12.2 95.23,78.26 T2.9
N80948331: length 2.4
  BOTTOM w0.508: VR2.1 73.15,53.47 R22.2

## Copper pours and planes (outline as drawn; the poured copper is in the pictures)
VCC on BOTTOM: 113.51,79.93 113.46,79.93 111.96,78.44 111.96,77.77 113.33,76.4 113.51,76.58
VCC on BOTTOM: 103.07,78.38 103.07,76.43 102.92,76.28 102.57,76.28 101.24,77.6 101.24,78.11 101.52,78.38
VCC on BOTTOM: 123.09,70.08 123.57,69.6 123.57,69.09 123.47,68.99 121.54,68.99 121.08,69.44 121.08,69.85 121.84,70.61 123.09,70.61
Net_29 on BOTTOM (solid shape): 126.19,8.89 126.19,2.21 125.3,1.32 121.67,1.32 120.47,2.51 120.47,8.71 122.02,10.26 124.82,10.26
N5956925 on BOTTOM: 22.4,9.75 22.99,10.34 24.71,10.34 25.22,9.83 25.22,9.09 25.68,8.64 45.57,8.64 55.68,18.75 55.68,24.94 57.38,26.64 67.69,26.64 67.72,26.67 72.24,26.67 72.69,26.21 72.69,24.87 69.67,21.84 69.67,15.44 73.81,11.3 90.12,11.3 90.65,10.77 90.65,9.83 90.12,9.3 73.18,9.3 66.95,15.52 59.49,15.52 50.52,6.55 22.89,6.55 22.4,7.04
N5956925 on BOTTOM: 53.98,67.61 54.56,67.03 56.49,67.03 57.15,67.69 57.07,67.69 56.88,67.88 56.9,67.89 56.9,68.76 56.88,68.77 55.99,68.77 54.81,69.95 53.39,69.95 53.39,68.71 53.37,68.71 52.73,68.07 52.73,67.59 53.95,67.59
N5956925 on BOTTOM: 57.77,47.26 58.72,46.3 66.88,46.3 67.87,45.31 70.56,45.31 71.22,45.97 72.16,45.97 72.52,45.62 72.52,44.6 72.34,44.42 66.55,44.42 65.61,45.36 63.22,45.36 62.23,44.37 61.54,44.37 60.83,45.09 57.38,45.09 56.36,46.1 56.36,49.99 56.62,50.24 57.51,50.24 57.77,49.97
N5956925 on BOTTOM: 56.74,79.45 77.47,79.45 77.47,77.44 73.56,77.44 71.53,75.41 58.8,75.41 58.32,74.93 56.18,74.93 55.71,75.4 55.71,78.4 55.7,78.41
N6451090 on BOTTOM: 109.22,12.01 109.22,18.52 109.21,18.53 109.21,19.09 108.2,20.09 104.6,20.09 104.6,20.12 103.53,21.18 103.53,28.19 104.48,29.15 119.06,29.15 125.35,35.43 125.35,47.9 126.14,48.69 126.14,54.31 127.15,55.32 127.97,55.32 127.98,55.31 141.87,55.31 142.77,54.41 142.77,43.33 140.28,40.84 138.28,40.84 137.41,41.71 137.41,52.58 137.08,52.91 130.76,52.91 130.38,52.53 130.38,27.36 122.02,19 117.6,19 117.14,19.46 117.14,20.22 117.63,20.7 117.63,23.83 117.07,24.38 113.16,24.38 111.51,22.73 111.51,11.02 105.54,5.05 98.65,5.05 97.99,5.72 97.99,6.91 98.63,7.54 104.75,7.54
N6451090 on BOTTOM: 95.43,72.67 96.55,72.67 96.75,72.47 96.75,71.7 96.52,71.48 95.43,72.57
N6900286 on BOTTOM: 66.52,35.64 68.73,35.64 68.99,35.38 68.99,35 68.63,34.65 68.63,32.74 68.12,32.23 67.31,32.23 66.75,32.79 66.75,34.57 66.37,34.95 66.34,34.95 66.34,35.46
N6900286 on BOTTOM: 39.55,53.47 35.33,53.47 34.7,52.83 34.7,41.86 32.99,40.16 32.99,23.09 31.34,21.44 20.52,21.44 20.05,20.97 20.05,20 20.62,19.43 21.67,19.43 21.95,19.71 33.07,19.71 35.15,21.79 35.15,28.55 36.47,29.87 36.47,38.07 40.06,41.66 45.52,41.66 47.85,39.32 47.85,32.16 48.21,31.8 51.38,31.8 52.1,32.51 52.1,33.81 51.92,33.99 51.31,33.99 49.99,35.31 49.99,41.48 45.16,46.3 45.16,54.43 44.6,54.99 41.07,54.99
N7093005 on BOTTOM: 144.65,38.53 146.1,37.08 155.8,37.08 156.74,38.02 156.74,46.99 146.96,56.77 146.13,56.77 144.65,55.3
N7093005 on BOTTOM: 146.76,63.65 146.76,64.19 146.43,64.52 146.05,64.52 145.26,63.73 145.21,63.73 144.58,64.36 144.58,64.77 144.83,65.02 147.27,65.02 147.62,64.67 147.62,64.52
N8059193 on BOTTOM: 32.61,74.35 34.09,74.35 34.87,73.56 34.87,65.99 29.44,60.55 29.44,54.36 30.99,52.81 30.99,45.82 25.45,40.28 10.97,40.28 8.43,42.82 8.43,47.47 8.92,47.96 10.34,47.96 11.13,47.17 11.13,44.22 12.24,43.1 24.26,43.1 28.27,47.12 28.27,50.85 26.09,53.04 26.09,61.44 31.9,67.26 31.9,73.63
N8059197 on BOTTOM: 5.31,74.47 16.21,74.47 16.74,73.94 16.74,72.09 16.36,71.7 5.28,71.7 5.16,71.83 5.16,74.32
N8059233 on BOTTOM: 20.26,36.74 29.92,27.08 29.92,24.87 29.21,24.16 24.94,24.16 20.94,28.16 20.92,28.16 18.69,30.38 18.69,33.58 17.73,34.54 17.73,35.86 18.61,36.74
N8059437 on BOTTOM: 5.97,66.65 20.35,66.65 21.23,65.76 21.23,59.11 18.77,56.64 18.77,53.77 21.08,51.46 21.08,46.51 20.27,45.69 19.18,45.69 18.36,46.51 18.36,50.04 16.26,52.15 11.94,52.15 11.3,52.78 11.3,54.38 17.73,60.81 17.73,62.56 16.51,63.78 5.89,63.78 5.28,64.39 5.28,65.96
N8059489 on BOTTOM: 10.87,36.17 10.87,35.05 10.24,34.42 10.24,31.01 9.08,29.86 9.08,27.95 14.86,22.17 14.86,18.16 15.37,17.65 29.03,17.65 29.87,16.81 29.87,14.86 29.21,14.2 28.24,14.2 27.69,14.76 27.69,15.65 27.38,15.95 13.74,15.95 12.93,16.76 12.93,21.21 5.38,28.75 5.38,33.5 8.81,36.93 10.11,36.93
N8060888 on BOTTOM: 39.57,16.48 40.54,16.48 41.28,15.75 41.28,14.71 37.16,10.59 27.08,10.59 25.48,12.19 21.95,12.19 20.29,10.54 20.29,8.53 19.46,7.7 12.98,7.7 12.32,8.36 12.32,10.01 12.33,10.02 12.33,10.35 12.99,11.01 17.26,11.01 20.27,14.02 26.19,14.02 27.51,12.7 35.79,12.7
N8067300 on BOTTOM: 135.23,39.95 139.78,35.41 156.24,35.41 156.95,34.7 156.95,19.1 155.42,17.58 145.54,17.58 143.64,19.48 143.64,24.16 139.9,27.89 133.55,27.89 131.88,29.57 131.88,50.95 132.92,51.99 134.04,51.99 135.23,50.8
N8070334 on BOTTOM: 115.19,66.09 115.19,67.03 115.21,67.06 115.7,67.06 116.13,66.62 115.32,65.81 115.14,65.81 115.14,66.04
N8071028 on BOTTOM: 130.78,65.84 132.38,65.84 132.51,65.96 132.87,65.96 133.12,65.71 132.87,65.46 132.61,65.46 131.8,64.64 131.52,64.64 130.56,65.61
N8073566 on BOTTOM: 42.06,29.36 42.05,29.35 42.05,27.9 41,26.85 38.84,26.85 38.33,26.34 38.33,22.35 39.17,21.51 51.46,21.51 52.04,22.1 52.04,24.41 51.99,24.41 51.26,25.15 48.16,25.15 45.26,28.04 45.26,38.66 44.45,39.47 42.88,39.47 42.06,38.66
N8088388 on BOTTOM: 20.22,74.45 27.79,74.45 28.6,73.63 28.6,72.42 27.94,71.76 20.04,71.76 19.43,72.36 19.43,73.66
N8194184 on BOTTOM: 61.67,36.65 61.67,29.41 62.36,28.73 67.36,28.73 67.39,28.7 75.92,28.7 78.69,25.93 83.46,25.93 84.25,26.72 84.25,28.19 83.46,28.98 80.49,28.98 78.36,31.12 64.8,31.12 63.91,32 63.91,36.55 64.03,36.68 65.53,36.68 65.61,36.75 65.61,37.52 65.53,37.59 62.61,37.59
N8194788 on BOTTOM: 64.03,54.36 65.18,54.36 65.86,53.67 65.86,49.48 65.61,49.23 63.6,49.23 63.4,49.43 63.4,53.72
N8194788 on BOTTOM: 80.8,54.51 82.32,54.51 84.38,52.45 84.38,45.9 84.33,45.85 81.23,45.85 81.13,45.95 81.13,52.1 80.44,52.78 80.44,54.15
N8195110 on BOTTOM: 68.63,56.49 68.63,47.52 68.38,47.27 66.78,47.27 66.7,47.35 66.7,48.18 67.11,48.59 67.11,54.66 66.19,55.58 66.19,56.92 66.78,57.51 67.61,57.51
N8195110 on BOTTOM: 77.61,65.34 68.53,56.26 67.51,56.26 66.73,57.05 66.73,57.45 75.11,65.84 75.11,67.79 75.87,68.55 77.37,68.55 77.6,68.33 77.6,65.53 77.61,65.52
N8203179 on BOTTOM: 121.36,44.37 121.36,34.82 120.37,33.83 117.53,33.83 117.22,34.14 117.22,35.08 117.68,35.53 117.68,38.94 116.74,39.88 108.79,39.88 107.06,38.15 107.06,36.7 106.17,35.81 104.57,35.81 103.4,36.98 103.4,43.51 105.11,45.21 120.52,45.21
N8204208 on BOTTOM: 66.67,43.41 70.51,43.41 70.56,43.36 70.56,42.49 70.51,42.44 66.7,42.44 66.5,42.65 66.5,43.23
N8207135 on BOTTOM: 71.91,37.03 75.29,37.03 77.8,34.52 80.29,34.52 80.29,32.44 80.26,32.41 75.18,32.41 74.83,32.77 74.83,34.37 74.14,35.05 72.01,35.05 71.7,35.36 71.68,35.36 71.68,36.8
N8207503 on BOTTOM: 66.67,38.56 70.13,38.56 71.04,37.64 71.04,33.05 71.02,33.02 70.23,33.02 70.21,33.05 70.21,37.11 69.65,37.67 66.67,37.67 66.52,37.82 66.52,38.4
N8207747 on BOTTOM: 62.36,40.64 62.53,40.46 65.05,40.46 65.3,40.21 65.3,39.75 65.1,39.55 61.49,39.55 60.96,39.01 60.93,39.01 60.88,38.96 60.88,37.52 60.5,37.13 59.84,37.13 59.49,37.49 59.49,40.59 59.54,40.64
N8207786 on BOTTOM: 69.62,41.48 66.37,41.48 66.07,41.17 66.07,40.79 66.32,40.54 69.65,40.54 69.72,40.61 69.72,41.38
N8210623 on BOTTOM: 38.53,60.93 39.22,60.93 40.51,59.64 40.51,58.42 41.15,57.78 45.31,57.78 45.82,57.28 45.82,56.26 45.47,55.91 39.14,55.91 38.13,56.92 38.13,60.53
N8210650 on BOTTOM: 67.34,70.61 68.86,70.61 68.91,70.56 68.91,70.28 66.75,68.12 66.75,70.03
N8210678 on BOTTOM: 50.67,57.71 55.68,57.71 56.11,57.28 56.11,55.09 51.36,55.09 50.27,56.18 50.27,57.3
N8215069 on BOTTOM: 63.58,44.32 65.3,44.32 65.53,44.09 65.53,43.61 65.25,43.33 59.97,43.33 59.46,42.82 58.04,42.82 58.01,42.85 58.01,44.35 59.59,44.35 60.07,43.87 63.12,43.87
N8289100 on BOTTOM: 112.85,13.41 112.85,22.61 113.46,23.22 115.9,23.22 116.33,22.78 116.33,17.98 117.73,16.59 123.34,16.59 123.34,16.71 132.08,25.45 139.42,25.45 141.99,22.89 141.99,13.11 140.67,11.79 114.48,11.79
N8289100 on BOTTOM: 115.7,35.36 115.7,31.04 115.01,30.35 113.39,30.35 113,30.73 113,37.95 113.41,38.35 116,38.35 116.28,38.07 116.28,35.94
N8290901 on BOTTOM: 109.55,37.8 111.58,37.8 111.96,37.41 111.96,32.46 111.91,32.46 111.28,31.83 109.96,31.83 109.14,32.64 109.14,37.39
N8358108 on BOTTOM: 81.74,32.51 81.74,37.85 82.37,38.48 83.64,38.48 84.43,37.69 84.43,32.92 83.97,32.46 81.79,32.46
N82099951 on BOTTOM: 35.48,60.99 36.75,60.99 37.47,60.27 37.47,55.73 37.41,55.68 34.95,55.68 34.9,55.73 34.9,60.4

Small or netless copper shapes (teardrops, artwork), in the pictures only: 5 on BOTTOM

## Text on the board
Ref Des/Silkscreen Top: TM | JP1 | JP2 | JP3 | JP4 | JP8 | 1532 | S/N | REV A | DER-483 | JP7 | JP6 | JP5 | JP9 | JP10 | JP11 | JP12 | JP14 | JP13 | RTN | +23V | HiperTFS-2
PAGE_OUTLINE: 13   MATERIAL FR4 COPPER 2oz THICKNESS 0.062" | SLOT
User.5: FIGURE | SIZE | 30.0 | 31.0 | 35.0 | 38.0 | 40.0 | 46.0 | 50.0 | 51.0 | 52.0 | 56.0 | 60.0 | 65.0 | 70.0 | 156.0 | DRILL CHART: TOP to BOTTOM | ALL UNITS ARE IN MILS | QTY | 38 | 14 | 20 | 2 | 42 | 8 | 10 | 13 | 4 | 9 | 7
